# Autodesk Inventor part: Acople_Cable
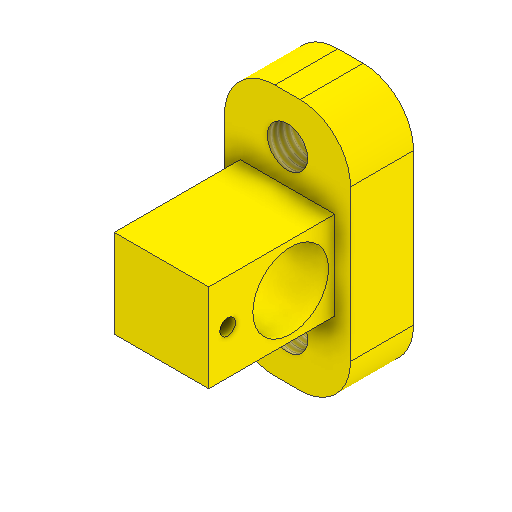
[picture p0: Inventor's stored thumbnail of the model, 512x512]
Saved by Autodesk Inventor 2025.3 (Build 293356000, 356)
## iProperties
Created: 2025-11
Part Number: Acople_Cable
Material: Genérico
Document SubType Name: Modeling
Designer: Dell
Density: 1 g/cm^3
Appearance: Valor por defecto
Author: Dell
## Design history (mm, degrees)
sketch "Boceto1"
  geometry: L1 (-10, 20)-(10, 20); L2 (10, 20)-(10, -20); L3 (10, -20)-(-10, -20); L4 (-10, -20)-(-10, 20); L5 (-10, 20)-(10, -20); L6 (10, 20)-(-10, -20); C1 r 3.2 at (0, 12.5); C2 r 3.2 at (0, -12.5); 1 further point
  constraints: 12 end point, 2 centre point, 2 midpoint, 2 parallel, 1 horizontal, 1 perpendicular
  dimensions: "d22" = 6.4 diameter of C1; "d23" = 6.4 diameter of C2
extrude "Extrusión1" new body sketch "Boceto1" distance "d6" = 10; taper "d7" = 0 deg
feature "Rosca1" dims "d8" = 80, "d9" = 0
feature "Rosca2" dims "d10" = 80, "d11" = 0
sketch "Boceto2"
  geometry: L1 (-7.5, 7)-(7.5, 7); L2 (7.5, 7)-(7.5, -7); L3 (7.5, -7)-(-7.5, -7); L4 (-7.5, -7)-(-7.5, 7); L5 (-7.5, 7)-(7.5, -7); L6 (7.5, 7)-(-7.5, -7); 1 further point
  constraints: 12 end point, 2 midpoint, 2 parallel, 1 horizontal, 1 perpendicular
  dimensions: "d26" = 15 distance of L2.end L3.end; "d27" = 14 distance of L1.end L2.end
extrude "Extrusión2" join sketch "Boceto2" distance "d14" = 20; taper "d15" = 0 deg
fillet "Empalme1" dims "d32" = 8
sketch "Boceto5"
  geometry: L1 (0, 14)-(0, 0) reference; C1 r 6 at (-7, 7); C2 r 1.25 at (-17, 7); 1 further point
  constraints: 2 centre point
  dimensions: "d41" = 12 diameter of C1; "d43" = 2.5 diameter of C2
extrude "Extrusión5" cut sketch "Boceto5" distance "d44" = 15; taper "d45" = 0 deg
node "Sólido1"
